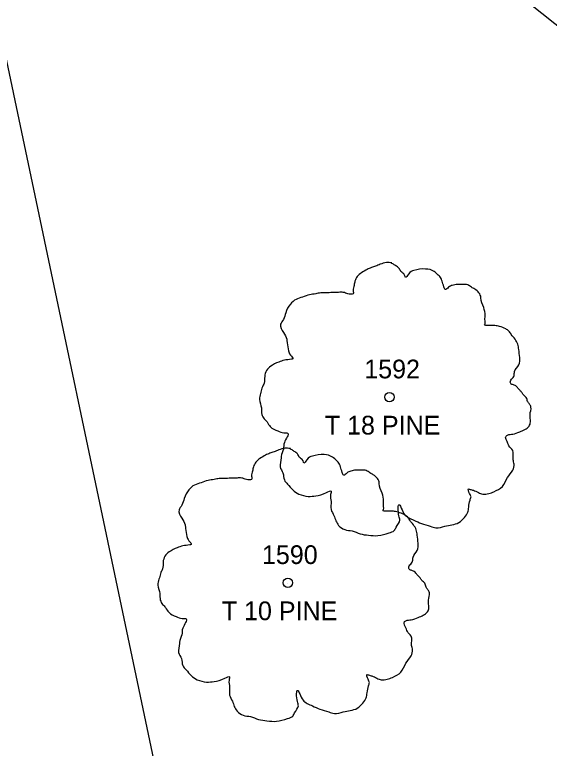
# Model space of a CAD drawing. Extents: x 1965304 to 1970247, y 1117014 to 1118201.
# Drawn here: x 1966670.03 to 1966698.59, y 1117457.62 to 1117496.81 of the extents above; entities that cross this region are included whole.
import ezdxf

# ---------------------------------------------------------------- set-up
doc = ezdxf.new("R2010")
doc.units = 0
for name, color, linetype in [('RD_EX_Driveway', 7, 'Continuous'), ('RD_EX_VEG', 7, 'Continuous'), ('RD_EX_VEG_txCode', 7, 'Continuous'), ('RD_HC_Data', 7, 'Continuous')]:
    doc.layers.add(name, color=color, linetype=linetype)

msp = doc.modelspace()

# ---------------------------------------------------------------- linework, layer by layer
at = {"layer": 'RD_EX_Driveway'}
msp.add_lwpolyline([(1966589.3, 1117436.331), (1966587.977, 1117456.65), (1966594.083, 1117483.042), (1966609.697, 1117504.074), (1966638.325, 1117518.314), (1966661.317, 1117517.134), (1966685.434, 1117507.038), (1966705.558, 1117491.043), (1966722.871, 1117472.119), (1966734.107, 1117458.19)], dxfattribs=at)
at = {"layer": 'RD_EX_VEG'}
for centre, radius in [((1966690.05, 1117476.387), 0.25), ((1966690.05, 1117476.387), 0.25), ((1966690.038, 1117476.368), 0.0001), ((1966690.038, 1117476.368), 0.0001), ((1966684.627, 1117466.469), 0.25), ((1966684.627, 1117466.469), 0.25), ((1966684.614, 1117466.45), 0.0001), ((1966684.614, 1117466.45), 0.0001)]:
    msp.add_circle(centre, radius, dxfattribs=at)
for points in [[(1966690.182, 1117483.554), (1966689.882, 1117483.579), (1966689.558, 1117483.479), (1966689.308, 1117483.379), (1966689.083, 1117483.304), (1966688.858, 1117483.204), (1966688.558, 1117483.029), (1966688.333, 1117482.829), (1966688.208, 1117482.579), (1966688.158, 1117482.355), (1966688.108, 1117482.08), (1966688.108, 1117481.905), (1966687.983, 1117481.88), (1966687.833, 1117481.905), (1966687.583, 1117481.98), (1966687.333, 1117481.98), (1966687.084, 1117481.98), (1966686.734, 1117481.955), (1966686.384, 1117481.955), (1966686.109, 1117481.905), (1966685.784, 1117481.855), (1966685.409, 1117481.73), (1966685.059, 1117481.605), (1966684.76, 1117481.355), (1966684.51, 1117480.88), (1966684.385, 1117480.53), (1966684.235, 1117480.28), (1966684.385, 1117479.831), (1966684.56, 1117479.481), (1966684.585, 1117479.281), (1966684.66, 1117478.856), (1966684.76, 1117478.631), (1966684.885, 1117478.431), (1966684.81, 1117478.406), (1966684.435, 1117478.356), (1966684.135, 1117478.256), (1966683.71, 1117478.031), (1966683.485, 1117477.807), (1966683.385, 1117477.482), (1966683.36, 1117477.132), (1966683.26, 1117476.932), (1966683.185, 1117476.657), (1966683.16, 1117476.582), (1966683.11, 1117476.257), (1966683.21, 1117475.807), (1966683.235, 1117475.458), (1966683.36, 1117475.233), (1966683.51, 1117475.058), (1966683.685, 1117474.808), (1966684.085, 1117474.583), (1966684.41, 1117474.483), (1966684.61, 1117474.458), (1966684.435, 1117473.958), (1966684.385, 1117473.608), (1966684.26, 1117473.209), (1966684.26, 1117473.134), (1966684.21, 1117472.659), (1966684.36, 1117472.334), (1966684.435, 1117471.959), (1966684.61, 1117471.734), (1966684.885, 1117471.434), (1966685.209, 1117471.209), (1966685.709, 1117471.084), (1966686.109, 1117471.109), (1966686.684, 1117471.284), (1966686.934, 1117471.359), (1966686.909, 1117471.184), (1966686.934, 1117470.81), (1966686.934, 1117470.385), (1966687.084, 1117470.06), (1966687.184, 1117469.785), (1966687.333, 1117469.535), (1966687.658, 1117469.31), (1966688.058, 1117469.235), (1966688.483, 1117469.085), (1966688.933, 1117469.01), (1966689.433, 1117468.985), (1966690.032, 1117469.135), (1966690.307, 1117469.26), (1966690.407, 1117469.435), (1966690.607, 1117469.81), (1966690.557, 1117470.035), (1966690.582, 1117470.635), (1966690.682, 1117470.46), (1966690.857, 1117470.11), (1966691.357, 1117469.81), (1966691.757, 1117469.635), (1966692.231, 1117469.485), (1966692.531, 1117469.41), (1966693.006, 1117469.485), (1966693.381, 1117469.56), (1966693.756, 1117469.685), (1966694.056, 1117469.96), (1966694.23, 1117470.235), (1966694.28, 1117470.51), (1966694.355, 1117470.885), (1966694.405, 1117471.059)], [(1966690.182, 1117483.554), (1966689.882, 1117483.579), (1966689.558, 1117483.479), (1966689.308, 1117483.379), (1966689.083, 1117483.304), (1966688.858, 1117483.204), (1966688.558, 1117483.029), (1966688.333, 1117482.829), (1966688.208, 1117482.579), (1966688.158, 1117482.355), (1966688.108, 1117482.08), (1966688.108, 1117481.905), (1966687.983, 1117481.88), (1966687.833, 1117481.905), (1966687.583, 1117481.98), (1966687.333, 1117481.98), (1966687.084, 1117481.98), (1966686.734, 1117481.955), (1966686.384, 1117481.955), (1966686.109, 1117481.905), (1966685.784, 1117481.855), (1966685.409, 1117481.73), (1966685.059, 1117481.605), (1966684.76, 1117481.355), (1966684.51, 1117480.88), (1966684.385, 1117480.53), (1966684.235, 1117480.28), (1966684.385, 1117479.831), (1966684.56, 1117479.481), (1966684.585, 1117479.281), (1966684.66, 1117478.856), (1966684.76, 1117478.631), (1966684.885, 1117478.431), (1966684.81, 1117478.406), (1966684.435, 1117478.356), (1966684.135, 1117478.256), (1966683.71, 1117478.031), (1966683.485, 1117477.807), (1966683.385, 1117477.482), (1966683.36, 1117477.132), (1966683.26, 1117476.932), (1966683.185, 1117476.657), (1966683.16, 1117476.582), (1966683.11, 1117476.257), (1966683.21, 1117475.807), (1966683.235, 1117475.458), (1966683.36, 1117475.233), (1966683.51, 1117475.058), (1966683.685, 1117474.808), (1966684.085, 1117474.583), (1966684.41, 1117474.483), (1966684.61, 1117474.458), (1966684.435, 1117473.958), (1966684.385, 1117473.608), (1966684.26, 1117473.209), (1966684.26, 1117473.134), (1966684.21, 1117472.659), (1966684.36, 1117472.334), (1966684.435, 1117471.959), (1966684.61, 1117471.734), (1966684.885, 1117471.434), (1966685.209, 1117471.209), (1966685.709, 1117471.084), (1966686.109, 1117471.109), (1966686.684, 1117471.284), (1966686.934, 1117471.359), (1966686.909, 1117471.184), (1966686.934, 1117470.81), (1966686.934, 1117470.385), (1966687.084, 1117470.06), (1966687.184, 1117469.785), (1966687.333, 1117469.535), (1966687.658, 1117469.31), (1966688.058, 1117469.235), (1966688.483, 1117469.085), (1966688.933, 1117469.01), (1966689.433, 1117468.985), (1966690.032, 1117469.135), (1966690.307, 1117469.26), (1966690.407, 1117469.435), (1966690.607, 1117469.81), (1966690.557, 1117470.035), (1966690.582, 1117470.635), (1966690.682, 1117470.46), (1966690.857, 1117470.11), (1966691.357, 1117469.81), (1966691.757, 1117469.635), (1966692.231, 1117469.485), (1966692.531, 1117469.41), (1966693.006, 1117469.485), (1966693.381, 1117469.56), (1966693.756, 1117469.685), (1966694.056, 1117469.96), (1966694.23, 1117470.235), (1966694.28, 1117470.51), (1966694.355, 1117470.885), (1966694.405, 1117471.059)], [(1966694.405, 1117471.059), (1966694.33, 1117471.234), (1966694.28, 1117471.484), (1966694.355, 1117471.459), (1966694.53, 1117471.409), (1966694.805, 1117471.284), (1966695.03, 1117471.209), (1966695.355, 1117471.234), (1966695.63, 1117471.334), (1966696.08, 1117471.609), (1966696.355, 1117472.084), (1966696.629, 1117472.484), (1966696.704, 1117472.809), (1966696.654, 1117473.034), (1966696.629, 1117473.533), (1966696.429, 1117473.783), (1966696.379, 1117473.908), (1966696.28, 1117474.308), (1966696.355, 1117474.358), (1966696.629, 1117474.408), (1966697.004, 1117474.533), (1966697.279, 1117474.658), (1966697.504, 1117474.833), (1966697.579, 1117475.058), (1966697.554, 1117475.458), (1966697.604, 1117475.857), (1966697.529, 1117476.007), (1966697.429, 1117476.157), (1966697.354, 1117476.357), (1966697.204, 1117476.507), (1966697.104, 1117476.657), (1966697.004, 1117476.757), (1966696.879, 1117476.907), (1966696.704, 1117477.032), (1966696.554, 1117477.082), (1966696.504, 1117477.232), (1966696.654, 1117477.432), (1966696.704, 1117477.532), (1966696.729, 1117477.757), (1966696.954, 1117478.106), (1966697.004, 1117478.506), (1966696.954, 1117478.931), (1966696.904, 1117479.206), (1966696.754, 1117479.481), (1966696.554, 1117479.731), (1966696.429, 1117479.906), (1966696.255, 1117480.031), (1966695.93, 1117480.156), (1966695.68, 1117480.205), (1966695.33, 1117480.205), (1966695.13, 1117480.255), (1966695.155, 1117480.305), (1966695.155, 1117480.455), (1966695.155, 1117480.73), (1966695.08, 1117481.18), (1966694.93, 1117481.68), (1966694.93, 1117481.705), (1966694.83, 1117481.955), (1966694.605, 1117482.155), (1966694.43, 1117482.255), (1966694.23, 1117482.38), (1966693.981, 1117482.405), (1966693.681, 1117482.405), (1966693.406, 1117482.355), (1966693.206, 1117482.255), (1966693.031, 1117482.13), (1966692.956, 1117482.28), (1966692.856, 1117482.579), (1966692.806, 1117482.729), (1966692.656, 1117482.904), (1966692.431, 1117483.104), (1966691.981, 1117483.229), (1966691.357, 1117483.154), (1966691.057, 1117482.954), (1966690.907, 1117482.779), (1966690.857, 1117482.904), (1966690.657, 1117483.104), (1966690.557, 1117483.279), (1966690.382, 1117483.404), (1966690.232, 1117483.504), (1966690.132, 1117483.554)], [(1966694.405, 1117471.059), (1966694.33, 1117471.234), (1966694.28, 1117471.484), (1966694.355, 1117471.459), (1966694.53, 1117471.409), (1966694.805, 1117471.284), (1966695.03, 1117471.209), (1966695.355, 1117471.234), (1966695.63, 1117471.334), (1966696.08, 1117471.609), (1966696.355, 1117472.084), (1966696.629, 1117472.484), (1966696.704, 1117472.809), (1966696.654, 1117473.034), (1966696.629, 1117473.533), (1966696.429, 1117473.783), (1966696.379, 1117473.908), (1966696.28, 1117474.308), (1966696.355, 1117474.358), (1966696.629, 1117474.408), (1966697.004, 1117474.533), (1966697.279, 1117474.658), (1966697.504, 1117474.833), (1966697.579, 1117475.058), (1966697.554, 1117475.458), (1966697.604, 1117475.857), (1966697.529, 1117476.007), (1966697.429, 1117476.157), (1966697.354, 1117476.357), (1966697.204, 1117476.507), (1966697.104, 1117476.657), (1966697.004, 1117476.757), (1966696.879, 1117476.907), (1966696.704, 1117477.032), (1966696.554, 1117477.082), (1966696.504, 1117477.232), (1966696.654, 1117477.432), (1966696.704, 1117477.532), (1966696.729, 1117477.757), (1966696.954, 1117478.106), (1966697.004, 1117478.506), (1966696.954, 1117478.931), (1966696.904, 1117479.206), (1966696.754, 1117479.481), (1966696.554, 1117479.731), (1966696.429, 1117479.906), (1966696.255, 1117480.031), (1966695.93, 1117480.156), (1966695.68, 1117480.205), (1966695.33, 1117480.205), (1966695.13, 1117480.255), (1966695.155, 1117480.305), (1966695.155, 1117480.455), (1966695.155, 1117480.73), (1966695.08, 1117481.18), (1966694.93, 1117481.68), (1966694.93, 1117481.705), (1966694.83, 1117481.955), (1966694.605, 1117482.155), (1966694.43, 1117482.255), (1966694.23, 1117482.38), (1966693.981, 1117482.405), (1966693.681, 1117482.405), (1966693.406, 1117482.355), (1966693.206, 1117482.255), (1966693.031, 1117482.13), (1966692.956, 1117482.28), (1966692.856, 1117482.579), (1966692.806, 1117482.729), (1966692.656, 1117482.904), (1966692.431, 1117483.104), (1966691.981, 1117483.229), (1966691.357, 1117483.154), (1966691.057, 1117482.954), (1966690.907, 1117482.779), (1966690.857, 1117482.904), (1966690.657, 1117483.104), (1966690.557, 1117483.279), (1966690.382, 1117483.404), (1966690.232, 1117483.504), (1966690.132, 1117483.554)], [(1966684.758, 1117473.636), (1966684.459, 1117473.661), (1966684.134, 1117473.561), (1966683.884, 1117473.461), (1966683.659, 1117473.386), (1966683.434, 1117473.286), (1966683.134, 1117473.111), (1966682.909, 1117472.911), (1966682.784, 1117472.661), (1966682.734, 1117472.436), (1966682.684, 1117472.162), (1966682.684, 1117471.987), (1966682.559, 1117471.962), (1966682.409, 1117471.987), (1966682.16, 1117472.062), (1966681.91, 1117472.062), (1966681.66, 1117472.062), (1966681.31, 1117472.037), (1966680.96, 1117472.037), (1966680.685, 1117471.987), (1966680.36, 1117471.937), (1966679.986, 1117471.812), (1966679.636, 1117471.687), (1966679.336, 1117471.437), (1966679.086, 1117470.962), (1966678.961, 1117470.612), (1966678.811, 1117470.362), (1966678.961, 1117469.913), (1966679.136, 1117469.563), (1966679.161, 1117469.363), (1966679.236, 1117468.938), (1966679.336, 1117468.713), (1966679.461, 1117468.513), (1966679.386, 1117468.488), (1966679.011, 1117468.438), (1966678.711, 1117468.338), (1966678.286, 1117468.113), (1966678.061, 1117467.888), (1966677.961, 1117467.563), (1966677.936, 1117467.214), (1966677.837, 1117467.014), (1966677.762, 1117466.739), (1966677.737, 1117466.664), (1966677.687, 1117466.339), (1966677.787, 1117465.889), (1966677.812, 1117465.539), (1966677.936, 1117465.314), (1966678.086, 1117465.14), (1966678.261, 1117464.89), (1966678.661, 1117464.665), (1966678.986, 1117464.565), (1966679.186, 1117464.54), (1966679.011, 1117464.04), (1966678.961, 1117463.69), (1966678.836, 1117463.29), (1966678.836, 1117463.215), (1966678.786, 1117462.741), (1966678.936, 1117462.416), (1966679.011, 1117462.041), (1966679.186, 1117461.816), (1966679.461, 1117461.516), (1966679.786, 1117461.291), (1966680.285, 1117461.166), (1966680.685, 1117461.191), (1966681.26, 1117461.366), (1966681.51, 1117461.441), (1966681.485, 1117461.266), (1966681.51, 1117460.891), (1966681.51, 1117460.467), (1966681.66, 1117460.142), (1966681.76, 1117459.867), (1966681.91, 1117459.617), (1966682.235, 1117459.392), (1966682.634, 1117459.317), (1966683.059, 1117459.167), (1966683.509, 1117459.092), (1966684.009, 1117459.067), (1966684.609, 1117459.217), (1966684.883, 1117459.342), (1966684.983, 1117459.517), (1966685.183, 1117459.892), (1966685.133, 1117460.117), (1966685.158, 1117460.717), (1966685.258, 1117460.542), (1966685.433, 1117460.192), (1966685.933, 1117459.892), (1966686.333, 1117459.717), (1966686.808, 1117459.567), (1966687.107, 1117459.492), (1966687.582, 1117459.567), (1966687.957, 1117459.642), (1966688.332, 1117459.767), (1966688.632, 1117460.042), (1966688.807, 1117460.317), (1966688.857, 1117460.592), (1966688.932, 1117460.966), (1966688.982, 1117461.141)], [(1966684.758, 1117473.636), (1966684.459, 1117473.661), (1966684.134, 1117473.561), (1966683.884, 1117473.461), (1966683.659, 1117473.386), (1966683.434, 1117473.286), (1966683.134, 1117473.111), (1966682.909, 1117472.911), (1966682.784, 1117472.661), (1966682.734, 1117472.436), (1966682.684, 1117472.162), (1966682.684, 1117471.987), (1966682.559, 1117471.962), (1966682.409, 1117471.987), (1966682.16, 1117472.062), (1966681.91, 1117472.062), (1966681.66, 1117472.062), (1966681.31, 1117472.037), (1966680.96, 1117472.037), (1966680.685, 1117471.987), (1966680.36, 1117471.937), (1966679.986, 1117471.812), (1966679.636, 1117471.687), (1966679.336, 1117471.437), (1966679.086, 1117470.962), (1966678.961, 1117470.612), (1966678.811, 1117470.362), (1966678.961, 1117469.913), (1966679.136, 1117469.563), (1966679.161, 1117469.363), (1966679.236, 1117468.938), (1966679.336, 1117468.713), (1966679.461, 1117468.513), (1966679.386, 1117468.488), (1966679.011, 1117468.438), (1966678.711, 1117468.338), (1966678.286, 1117468.113), (1966678.061, 1117467.888), (1966677.961, 1117467.563), (1966677.936, 1117467.214), (1966677.837, 1117467.014), (1966677.762, 1117466.739), (1966677.737, 1117466.664), (1966677.687, 1117466.339), (1966677.787, 1117465.889), (1966677.812, 1117465.539), (1966677.936, 1117465.314), (1966678.086, 1117465.14), (1966678.261, 1117464.89), (1966678.661, 1117464.665), (1966678.986, 1117464.565), (1966679.186, 1117464.54), (1966679.011, 1117464.04), (1966678.961, 1117463.69), (1966678.836, 1117463.29), (1966678.836, 1117463.215), (1966678.786, 1117462.741), (1966678.936, 1117462.416), (1966679.011, 1117462.041), (1966679.186, 1117461.816), (1966679.461, 1117461.516), (1966679.786, 1117461.291), (1966680.285, 1117461.166), (1966680.685, 1117461.191), (1966681.26, 1117461.366), (1966681.51, 1117461.441), (1966681.485, 1117461.266), (1966681.51, 1117460.891), (1966681.51, 1117460.467), (1966681.66, 1117460.142), (1966681.76, 1117459.867), (1966681.91, 1117459.617), (1966682.235, 1117459.392), (1966682.634, 1117459.317), (1966683.059, 1117459.167), (1966683.509, 1117459.092), (1966684.009, 1117459.067), (1966684.609, 1117459.217), (1966684.883, 1117459.342), (1966684.983, 1117459.517), (1966685.183, 1117459.892), (1966685.133, 1117460.117), (1966685.158, 1117460.717), (1966685.258, 1117460.542), (1966685.433, 1117460.192), (1966685.933, 1117459.892), (1966686.333, 1117459.717), (1966686.808, 1117459.567), (1966687.107, 1117459.492), (1966687.582, 1117459.567), (1966687.957, 1117459.642), (1966688.332, 1117459.767), (1966688.632, 1117460.042), (1966688.807, 1117460.317), (1966688.857, 1117460.592), (1966688.932, 1117460.966), (1966688.982, 1117461.141)], [(1966688.982, 1117461.141), (1966688.907, 1117461.316), (1966688.857, 1117461.566), (1966688.932, 1117461.541), (1966689.107, 1117461.491), (1966689.381, 1117461.366), (1966689.606, 1117461.291), (1966689.931, 1117461.316), (1966690.206, 1117461.416), (1966690.656, 1117461.691), (1966690.931, 1117462.166), (1966691.206, 1117462.566), (1966691.281, 1117462.891), (1966691.231, 1117463.115), (1966691.206, 1117463.615), (1966691.006, 1117463.865), (1966690.956, 1117463.99), (1966690.856, 1117464.39), (1966690.931, 1117464.44), (1966691.206, 1117464.49), (1966691.58, 1117464.615), (1966691.855, 1117464.74), (1966692.08, 1117464.915), (1966692.155, 1117465.14), (1966692.13, 1117465.539), (1966692.18, 1117465.939), (1966692.105, 1117466.089), (1966692.005, 1117466.239), (1966691.93, 1117466.439), (1966691.78, 1117466.589), (1966691.68, 1117466.739), (1966691.58, 1117466.839), (1966691.456, 1117466.989), (1966691.281, 1117467.114), (1966691.131, 1117467.164), (1966691.081, 1117467.314), (1966691.231, 1117467.514), (1966691.281, 1117467.613), (1966691.306, 1117467.838), (1966691.531, 1117468.188), (1966691.58, 1117468.588), (1966691.531, 1117469.013), (1966691.481, 1117469.288), (1966691.331, 1117469.563), (1966691.131, 1117469.813), (1966691.006, 1117469.987), (1966690.831, 1117470.112), (1966690.506, 1117470.237), (1966690.256, 1117470.287), (1966689.906, 1117470.287), (1966689.706, 1117470.337), (1966689.731, 1117470.387), (1966689.731, 1117470.537), (1966689.731, 1117470.812), (1966689.656, 1117471.262), (1966689.506, 1117471.762), (1966689.506, 1117471.787), (1966689.406, 1117472.037), (1966689.182, 1117472.236), (1966689.007, 1117472.336), (1966688.807, 1117472.461), (1966688.557, 1117472.486), (1966688.257, 1117472.486), (1966687.982, 1117472.436), (1966687.782, 1117472.336), (1966687.607, 1117472.211), (1966687.532, 1117472.361), (1966687.432, 1117472.661), (1966687.382, 1117472.811), (1966687.232, 1117472.986), (1966687.008, 1117473.186), (1966686.558, 1117473.311), (1966685.933, 1117473.236), (1966685.633, 1117473.036), (1966685.483, 1117472.861), (1966685.433, 1117472.986), (1966685.233, 1117473.186), (1966685.133, 1117473.361), (1966684.958, 1117473.486), (1966684.808, 1117473.586), (1966684.708, 1117473.636)], [(1966688.982, 1117461.141), (1966688.907, 1117461.316), (1966688.857, 1117461.566), (1966688.932, 1117461.541), (1966689.107, 1117461.491), (1966689.381, 1117461.366), (1966689.606, 1117461.291), (1966689.931, 1117461.316), (1966690.206, 1117461.416), (1966690.656, 1117461.691), (1966690.931, 1117462.166), (1966691.206, 1117462.566), (1966691.281, 1117462.891), (1966691.231, 1117463.115), (1966691.206, 1117463.615), (1966691.006, 1117463.865), (1966690.956, 1117463.99), (1966690.856, 1117464.39), (1966690.931, 1117464.44), (1966691.206, 1117464.49), (1966691.58, 1117464.615), (1966691.855, 1117464.74), (1966692.08, 1117464.915), (1966692.155, 1117465.14), (1966692.13, 1117465.539), (1966692.18, 1117465.939), (1966692.105, 1117466.089), (1966692.005, 1117466.239), (1966691.93, 1117466.439), (1966691.78, 1117466.589), (1966691.68, 1117466.739), (1966691.58, 1117466.839), (1966691.456, 1117466.989), (1966691.281, 1117467.114), (1966691.131, 1117467.164), (1966691.081, 1117467.314), (1966691.231, 1117467.514), (1966691.281, 1117467.613), (1966691.306, 1117467.838), (1966691.531, 1117468.188), (1966691.58, 1117468.588), (1966691.531, 1117469.013), (1966691.481, 1117469.288), (1966691.331, 1117469.563), (1966691.131, 1117469.813), (1966691.006, 1117469.987), (1966690.831, 1117470.112), (1966690.506, 1117470.237), (1966690.256, 1117470.287), (1966689.906, 1117470.287), (1966689.706, 1117470.337), (1966689.731, 1117470.387), (1966689.731, 1117470.537), (1966689.731, 1117470.812), (1966689.656, 1117471.262), (1966689.506, 1117471.762), (1966689.506, 1117471.787), (1966689.406, 1117472.037), (1966689.182, 1117472.236), (1966689.007, 1117472.336), (1966688.807, 1117472.461), (1966688.557, 1117472.486), (1966688.257, 1117472.486), (1966687.982, 1117472.436), (1966687.782, 1117472.336), (1966687.607, 1117472.211), (1966687.532, 1117472.361), (1966687.432, 1117472.661), (1966687.382, 1117472.811), (1966687.232, 1117472.986), (1966687.008, 1117473.186), (1966686.558, 1117473.311), (1966685.933, 1117473.236), (1966685.633, 1117473.036), (1966685.483, 1117472.861), (1966685.433, 1117472.986), (1966685.233, 1117473.186), (1966685.133, 1117473.361), (1966684.958, 1117473.486), (1966684.808, 1117473.586), (1966684.708, 1117473.636)]]:
    msp.add_spline(points, degree=3, dxfattribs=at)
at = {"layer": 'RD_HC_Data'}
msp.add_line((1966684.871, 1117421.945), (1966660.825, 1117536.006), dxfattribs=at)

# ---------------------------------------------------------------- texts
at = {"layer": 'RD_EX_VEG_txCode'}
for s, p in [('1592', (1966688.704, 1117477.387)), ('1592', (1966688.704, 1117477.387)), ('T 18 PINE', (1966686.598, 1117474.387)), ('T 18 PINE', (1966686.598, 1117474.387)), ('1590', (1966683.241, 1117467.469)), ('1590', (1966683.241, 1117467.469)), ('T 10 PINE', (1966681.095, 1117464.469)), ('T 10 PINE', (1966681.095, 1117464.469))]:
    msp.add_text(s, height=1, dxfattribs=at).set_placement(p)

doc.saveas('drawing.dxf')
